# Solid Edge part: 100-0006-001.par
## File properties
Title: 100-0006-00.par
Author: rkriggs
Template: Normal.par
Last saved by: jccrumbl
Revision: 42
Application: Solid Edge
Revision: A
Teamcenter Item Type: Item
Accuracy: 0.99
TC Engineering Description: Valve Handle
TC_ImportTime: 2008-07-08
PartType: -
Last Saved Version: -
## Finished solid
Body 1: solid body, 28 faces, 58 edges, 32 vertices.
  Faces by surface: plane 11, cylinder 8, blend 6, torus 3
  Edges by curve: circle 26, line 20, intersection 12
Bounding box of the edges (mm; curved faces can reach further): 96.166 x 46.000 x 18.000, from (-51.166, -23, -9) to (45, 23, 9).
Cylindrical faces by radius (mm): R2.5 x1, R5 x4, R7.5 x2, R18 x1
Toroidal faces (ring radius, tube radius in mm): R1.834 r23 x1, R25.1578 r2 x2
Planar faces by outward normal: +x 2, +y 2, +z 3, -y 2, -z 2
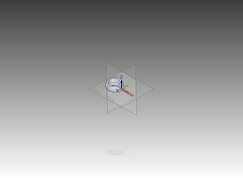
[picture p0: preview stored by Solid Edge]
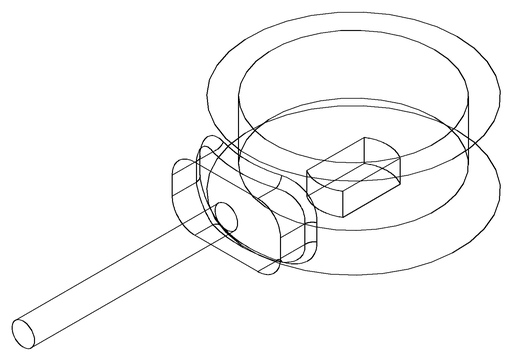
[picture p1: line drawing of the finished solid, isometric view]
